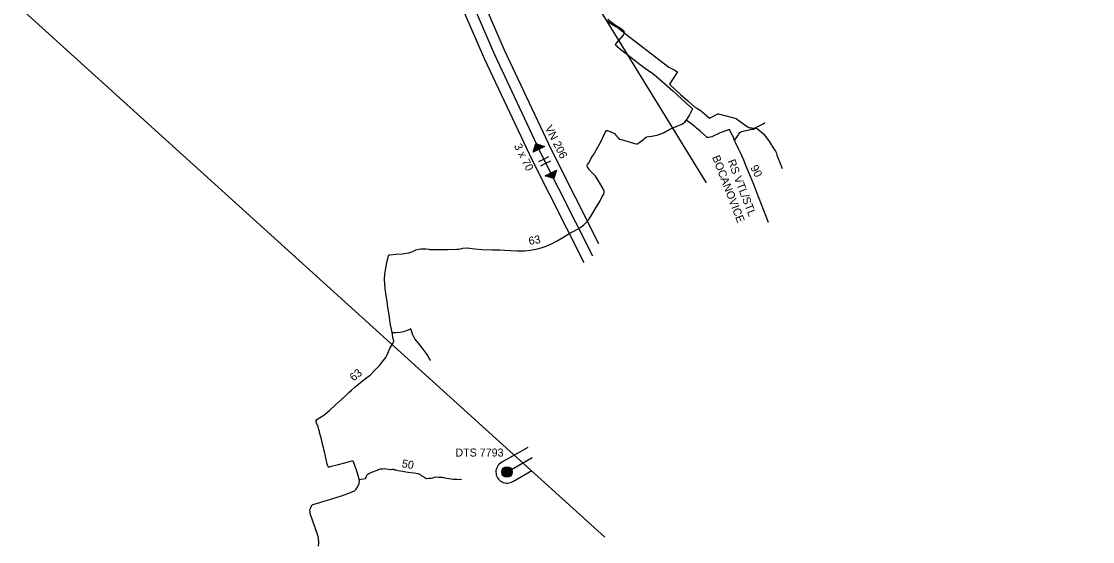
# Model space of a CAD drawing. Extents: x -444817 to -434929, y -1145681 to -1129851.
# Drawn here: x -441925 to -440854, y -1132496 to -1131975 of the extents above; entities that cross this region are included whole.
import ezdxf

# ---------------------------------------------------------------- set-up
doc = ezdxf.new("R2010")
doc.units = 0
for name, color, linetype in [('Vrstva 10', 7, 'Continuous'), ('Vrstva 11', 7, 'Continuous'), ('Vrstva 13', 7, 'Continuous'), ('Vrstva 15', 7, 'Continuous'), ('Vrstva 27', 7, 'Continuous'), ('Vrstva 29', 7, 'Continuous'), ('Vrstva 30', 7, 'Continuous'), ('Vrstva 58', 7, 'Continuous'), ('Vrstva 59', 7, 'Continuous')]:
    doc.layers.add(name, color=color, linetype=linetype)

msp = doc.modelspace()

# ---------------------------------------------------------------- linework, layer by layer
at = {"layer": 'Vrstva 10'}
for p, q in [((-441402.8, -1132112.7), (-441397.8, -1132110.2)), ((-441407.8, -1132115.2), (-441402.8, -1132112.7)), ((-441405.7, -1132119.5), (-441400.7, -1132116.9)), ((-441400.7, -1132116.9), (-441395.7, -1132114.4))]:
    msp.add_line(p, q, dxfattribs=at)
for points in [[(-441640.9, -1131756.1), (-441574.9, -1131839.7), (-441494.5, -1131910), (-441452.1, -1132008.2), (-441405, -1132108.4), (-441354, -1132209.5)], [(-441395.7, -1132126.7), (-441401.7, -1132114.8), (-441407.7, -1132102.9)], [(-441414.4, -1132411.6), (-441439, -1132426.1)]]:
    msp.add_lwpolyline(points, dxfattribs=at)
for points in [[(-441413.3, -1132105.8), (-441410.6, -1132097.3), (-441402.1, -1132100.1)], [(-441412.1, -1132104.4), (-441410.1, -1132098.2), (-441403.9, -1132100.2)], [(-441411, -1132103), (-441409.7, -1132099.1), (-441405.7, -1132100.4)], [(-441409.8, -1132101.6), (-441409.2, -1132100), (-441407.6, -1132100.5)], [(-441401.4, -1132129.5), (-441390.1, -1132123.9), (-441392.9, -1132132.3)], [(-441399.5, -1132129.4), (-441391.3, -1132125.2), (-441393.3, -1132131.4)], [(-441397.7, -1132129.3), (-441392.5, -1132126.6), (-441393.8, -1132130.6)], [(-441395.9, -1132129.1), (-441393.7, -1132128), (-441394.2, -1132129.7)]]:
    msp.add_lwpolyline(points, close=True, dxfattribs=at)
at = {"layer": 'Vrstva 11'}
for radius in [5.25, 4.55, 3.85, 3.15, 2.45, 1.75, 1.05, 0.35]:
    msp.add_circle((-441439.6, -1132425.9), radius, dxfattribs=at)
at = {"layer": 'Vrstva 15'}
for points in [[(-441649.5, -1131763), (-441582.9, -1131847.3), (-441503.6, -1131916.6), (-441462.1, -1132012.7), (-441414.9, -1132113.2), (-441362.9, -1132216.2)], [(-441347.7, -1132197.5), (-441395.1, -1132103.5), (-441442.1, -1132003.7), (-441485.4, -1131903.4), (-441566.9, -1131832.1), (-441625.3, -1131758.2)], [(-441418.9, -1132401.4), (-441444.8, -1132416.1)], [(-441433.2, -1132435), (-441414.6, -1132424.4)]]:
    msp.add_lwpolyline(points, dxfattribs=at)
msp.add_arc((-441439.6, -1132425.9), 11.1, 118.2404, 304.8832, dxfattribs=at)
at = {"layer": 'Vrstva 27'}
for points in [[(-441338.7, -1131972.8), (-441335.6, -1131975.5), (-441331.2, -1131978.7), (-441326.1, -1131981.7), (-441323.2, -1131984.2), (-441322.8, -1131985.2), (-441322.6, -1131986.4), (-441323, -1131988), (-441323.8, -1131989.1), (-441330.4, -1131996.8), (-441331, -1131997.7), (-441331.4, -1131998.2), (-441330.7, -1131998.7), (-441329.6, -1131999.7), (-441329.3, -1132000)], [(-441329.3, -1132000), (-441327.5, -1132001.7), (-441306.6, -1132018.2), (-441299.8, -1132023.1), (-441294.2, -1132026.9), (-441290.2, -1132030.1), (-441273.9, -1132044.3), (-441260.3, -1132056.8), (-441254.2, -1132062.3), (-441255.7, -1132065.9), (-441257.1, -1132068.5), (-441260.4, -1132073.8)], [(-441295.1, -1132089.8), (-441289.5, -1132088.7), (-441283.1, -1132086.4), (-441276.7, -1132082.9), (-441264.2, -1132077.5), (-441262.8, -1132076.6), (-441261.8, -1132075.7), (-441260.4, -1132073.8)], [(-441250, -1132081.8), (-441251.9, -1132080.1), (-441258.6, -1132075.3), (-441260.4, -1132073.8)], [(-441212, -1132094), (-441211.5, -1132093.3), (-441210.5, -1132091.9), (-441208.9, -1132089.4), (-441207.6, -1132087.3), (-441206.8, -1132086.2), (-441205.9, -1132085.5), (-441205, -1132085.3), (-441200.6, -1132084.3), (-441196.4, -1132083.3), (-441194.4, -1132082.9), (-441193.1, -1132082.7), (-441192.2, -1132082.3), (-441191.3, -1132081.6), (-441183.6, -1132077.4), (-441181.7, -1132076.1)], [(-441554.5, -1132286.4), (-441556.1, -1132278.5), (-441557.4, -1132268.7), (-441558.7, -1132260.8), (-441559.4, -1132254.8), (-441560.3, -1132249.5), (-441561.4, -1132242.4), (-441562, -1132233.4), (-441561.8, -1132227.5), (-441560.7, -1132222.1), (-441559.6, -1132215.9), (-441558.8, -1132212.6), (-441558.3, -1132210.9), (-441558, -1132209.2), (-441557.8, -1132208.9), (-441556.8, -1132208.7), (-441550.5, -1132207.9), (-441544.5, -1132207.6), (-441537.7, -1132206.6), (-441534.6, -1132205.7), (-441533, -1132204.8), (-441530.6, -1132203.5), (-441527.7, -1132202.9), (-441525.6, -1132202.5), (-441520.8, -1132202.7), (-441517.8, -1132202.9), (-441516.6, -1132203.2), (-441516.1, -1132203.3), (-441515.4, -1132203.3), (-441506, -1132203.2), (-441498.3, -1132203.1), (-441489.9, -1132202.9), (-441487.9, -1132202.8), (-441486.1, -1132202.7), (-441483.8, -1132201.8), (-441479.5, -1132201.6), (-441471.7, -1132202.5), (-441464.8, -1132203.2), (-441454.2, -1132203.7), (-441446.9, -1132203.6), (-441442.2, -1132203.8), (-441436.5, -1132204.1), (-441429.6, -1132204.6), (-441422.1, -1132204.7), (-441416.4, -1132204), (-441410.5, -1132202.9), (-441405.5, -1132201.6), (-441400.3, -1132199.8), (-441395.1, -1132197.4), (-441389.5, -1132194.5), (-441383.8, -1132191.1), (-441378.3, -1132187.8), (-441372.7, -1132184.9), (-441366.7, -1132181.4), (-441363.2, -1132178.9), (-441360.4, -1132176.2), (-441357.7, -1132173.1), (-441355, -1132168.8), (-441350.7, -1132161.6), (-441348.5, -1132157.9), (-441346.4, -1132154.4), (-441344.3, -1132150.3), (-441342.7, -1132147.9), (-441342.3, -1132146.3), (-441342.5, -1132144.7), (-441343.6, -1132142.5), (-441347.2, -1132136.2), (-441351.1, -1132130), (-441354.5, -1132126.5), (-441357.3, -1132123.2), (-441359.1, -1132120.6), (-441359.5, -1132120), (-441359.5, -1132119.4), (-441359.1, -1132118.3), (-441357.6, -1132116), (-441355.3, -1132111.9), (-441354, -1132109.8), (-441353.2, -1132108.5), (-441346.1, -1132096.2), (-441341.3, -1132086.3), (-441340.3, -1132084.4), (-441340, -1132084.2), (-441339.3, -1132084.3), (-441336.3, -1132085.2), (-441332.7, -1132086.7), (-441332.1, -1132087), (-441331, -1132088.4), (-441328.4, -1132091.6), (-441327.3, -1132092.8), (-441325.3, -1132093.3), (-441321.9, -1132094), (-441317.5, -1132095.4), (-441312.1, -1132097.2), (-441310.1, -1132097.5), (-441308.8, -1132097.4), (-441307.7, -1132096.6), (-441302.9, -1132092.7), (-441301.8, -1132091.7), (-441300.5, -1132090.9), (-441299.9, -1132090.6), (-441295.1, -1132089.8)], [(-441216, -1132085.4), (-441217.1, -1132083), (-441226.5, -1132086.5), (-441234.9, -1132090.4), (-441238.1, -1132091), (-441239.5, -1132091), (-441243.1, -1132087.7), (-441246.4, -1132084.9), (-441250, -1132081.8)], [(-441178.1, -1132176.3), (-441189.9, -1132146.2), (-441192.9, -1132138.2), (-441196, -1132130.1), (-441200, -1132120.9), (-441202.9, -1132113.9), (-441204.6, -1132110.2), (-441205.9, -1132107.3), (-441208.2, -1132102.6), (-441211, -1132096), (-441212, -1132094), (-441213.6, -1132090.3), (-441216, -1132085.4)], [(-441587.3, -1132433.3), (-441587.7, -1132431.8), (-441588.4, -1132429.3), (-441589.6, -1132425.1), (-441591.9, -1132418.3), (-441592.7, -1132416.3), (-441593.2, -1132415.7), (-441594.1, -1132415.2), (-441595, -1132415), (-441597.4, -1132415.7), (-441603.3, -1132417.3), (-441608.5, -1132418.7), (-441616.5, -1132420.7), (-441617.5, -1132421), (-441618, -1132420.9), (-441618.4, -1132420.7), (-441619.3, -1132417.9), (-441621.1, -1132410), (-441622.2, -1132405.4), (-441622.6, -1132403.4), (-441623.2, -1132401.3), (-441623.7, -1132399.3), (-441625.1, -1132393), (-441626.9, -1132386.2), (-441627.1, -1132385.3), (-441627.6, -1132383.4), (-441628.4, -1132380.6), (-441629.9, -1132377), (-441630.3, -1132375.4), (-441630.3, -1132374.5), (-441629.8, -1132373.4), (-441628.8, -1132372.7), (-441622.6, -1132369), (-441616.9, -1132364.5), (-441610.9, -1132358.8), (-441605.1, -1132353.4), (-441600.3, -1132349.1), (-441597.7, -1132346.3), (-441595.1, -1132343.9), (-441591.5, -1132340.8), (-441582.5, -1132333.4), (-441576.2, -1132328.5), (-441572, -1132324.4), (-441567.1, -1132319.3), (-441563.5, -1132314.6), (-441560.8, -1132311.3), (-441558.8, -1132306.9), (-441556.4, -1132301.7), (-441553.3, -1132296.6), (-441552.7, -1132295.4), (-441552.6, -1132294.7), (-441552.9, -1132293.9), (-441553.8, -1132291.1), (-441554.1, -1132288.4), (-441554.5, -1132286.4)], [(-441554.5, -1132286.4), (-441550.9, -1132286.2), (-441546.5, -1132285.9), (-441542.7, -1132285.3), (-441539, -1132284.1), (-441536.3, -1132282.8)], [(-441515.8, -1132314), (-441516.2, -1132314.1), (-441516.5, -1132313.9), (-441516.9, -1132313.5), (-441518.4, -1132309.9), (-441520.4, -1132307), (-441523.5, -1132303.1), (-441528.2, -1132296.9), (-441531.6, -1132292.5), (-441534, -1132287.8), (-441535.3, -1132283.2), (-441535.6, -1132282.8), (-441535.9, -1132282.7), (-441536.3, -1132282.8)], [(-441587.3, -1132433.3), (-441585.3, -1132432.9), (-441580.9, -1132432.3), (-441580.8, -1132432.2), (-441580.6, -1132432.1), (-441580.6, -1132431.7), (-441580.2, -1132430), (-441579.8, -1132429.1), (-441578.7, -1132428), (-441577.1, -1132426.9), (-441573.1, -1132425.3), (-441569.4, -1132423.9), (-441568.3, -1132423.4), (-441567, -1132422.9), (-441566.2, -1132422.8), (-441565.2, -1132422.7), (-441564.2, -1132422.6), (-441562.5, -1132422.5), (-441560.4, -1132422.6), (-441556.2, -1132423.4), (-441555.3, -1132423.5), (-441554, -1132423.1), (-441553.2, -1132423.1), (-441552.6, -1132423.4), (-441551.9, -1132423.6), (-441551.1, -1132423.8), (-441548.6, -1132424.3), (-441543.7, -1132424.9), (-441540.8, -1132425.6), (-441535.9, -1132426.4), (-441532.5, -1132426.7), (-441528.9, -1132427.3), (-441527.7, -1132427.6), (-441526.6, -1132428.2), (-441525.5, -1132429.4), (-441521.9, -1132431.5), (-441520.7, -1132432.2), (-441520.1, -1132432.4), (-441519.3, -1132432.4), (-441517.8, -1132432), (-441515.3, -1132431.9), (-441513.6, -1132431.6), (-441512.1, -1132431.1), (-441510.2, -1132430.7), (-441508.2, -1132430.9), (-441504.4, -1132431.1), (-441503.1, -1132431.4), (-441502, -1132431.8), (-441497.7, -1132432.4), (-441493, -1132433.1), (-441489.8, -1132433.2), (-441487.5, -1132433.5), (-441486, -1132433.2), (-441485.1, -1132433.1)], [(-441628, -1132500), (-441627.7, -1132496.7), (-441628, -1132491.8), (-441629.1, -1132488.4), (-441636.5, -1132467.4), (-441636.5, -1132465.9), (-441636.6, -1132463.8), (-441636, -1132462.4), (-441635.5, -1132460.4), (-441634.7, -1132459.3), (-441633.6, -1132458.3), (-441629.9, -1132457.3), (-441622.4, -1132455.1), (-441613.7, -1132452.5), (-441605.1, -1132449.7), (-441598.6, -1132447.4), (-441594.3, -1132445.7), (-441591.9, -1132444.6), (-441590.3, -1132443), (-441588.7, -1132440.5), (-441587.4, -1132437.3), (-441587.2, -1132435.1), (-441587.3, -1132433.3)]]:
    msp.add_lwpolyline(points, dxfattribs=at)
at = {"layer": 'Vrstva 58'}
for points in [[(-441339.7, -1131973.9), (-441335.9, -1131977), (-441330.7, -1131980.1), (-441329.8, -1131980.5), (-441319.7, -1131988.4), (-441283.4, -1132016.4), (-441277.9, -1132020.7), (-441271.9, -1132023.9), (-441270.4, -1132024.9), (-441269, -1132025.4), (-441277.1, -1132037.8), (-441276.6, -1132038.6), (-441265.8, -1132048.3), (-441259.1, -1132054), (-441252.1, -1132060.4), (-441249.7, -1132061.9), (-441245.6, -1132064.5), (-441244.9, -1132065.2), (-441237.2, -1132071.7), (-441235.8, -1132071.2), (-441228.8, -1132067.6), (-441228.2, -1132067.3), (-441220.5, -1132069.6), (-441210.6, -1132072.2), (-441206.4, -1132075.3), (-441198.5, -1132080.7), (-441196.7, -1132081.5), (-441194.9, -1132081.6), (-441192.3, -1132081.7), (-441190.3, -1132081.8), (-441189, -1132082.4), (-441183.2, -1132087.4), (-441181.9, -1132089.2)], [(-441181.9, -1132089.2), (-441177.1, -1132095.5), (-441173.4, -1132101.6), (-441171, -1132104.9), (-441169.9, -1132107.4), (-441170.3, -1132108.1), (-441166.8, -1132116.2), (-441164.6, -1132122.3)]]:
    msp.add_lwpolyline(points, dxfattribs=at)
at = {"layer": 'Vrstva 59'}
for points in [[(-443357.8, -1130664.3), (-442622.2, -1131330.9), (-441886.7, -1131997.4), (-441341.9, -1132491)], [(-440854.1, -1131064.1), (-441457.6, -1131782.5), (-441240.6, -1132136.5)]]:
    msp.add_lwpolyline(points, dxfattribs=at)

# ---------------------------------------------------------------- texts
at = {"layer": 'Vrstva 13'}
for s, p in [('VN 206', (-441401.9, -1132081.3)), ('3 x 70', (-441432.8, -1132099.5))]:
    msp.add_text(s, height=8, rotation=296.7619, dxfattribs=at).set_placement(p)
msp.add_text('DTS 7793', height=8, dxfattribs=at).set_placement((-441491.2, -1132410.4))
at = {"layer": 'Vrstva 29'}
for s, p in [('BOCANOVICE', (-441234.7, -1132110.8)), (' RS VTL/STL', (-441220.3, -1132112))]:
    msp.add_text(s, height=8, rotation=291.1048, dxfattribs=at).set_placement(p)
at = {"layer": 'Vrstva 30'}
for s, rotation, p in [('90', 298.0894, (-441196.5, -1132121.3)), ('63', 10.6902, (-441417.2, -1132198.8)), ('63', 39.3169, (-441592.9, -1132335.5)), ('50', 349.9291, (-441545.2, -1132421))]:
    msp.add_text(s, height=8, rotation=rotation, dxfattribs=at).set_placement(p)

doc.saveas('drawing.dxf')
